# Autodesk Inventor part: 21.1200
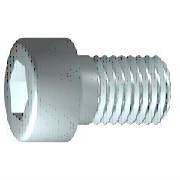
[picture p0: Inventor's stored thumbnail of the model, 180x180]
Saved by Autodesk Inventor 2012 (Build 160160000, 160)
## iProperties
Created: 2006-02
Part Number: 21.1200
Material: Steel, Mild
Description: M8 x 16 SHCS
Document SubType Name: Modeling
Standard: DIN 7984
Designer: Andy Moles
Standards Organization: DIN
Language: en-US
Size Designation: M8 x 16
Categories: <MemberInstance><Categories><Category DisplayName="Fasteners" InternalName="e4da775c-781d-43d5-af7c-5136215cf5a6" Mnemonic="FSTN"><Category DisplayName="Bolts"
Density: 7.86 g/cm^3
Mass: 10.6827 g
Surface Area: 9.17139 cm^2
Volume: 1.35912 cm^3
Vendor: S
Author: Andy Moles
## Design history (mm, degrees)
body "Solid1"
workplane "Work Plane1"
revolve "Body" stored, may be unused: angle "d10" = 90 deg
sketch "Sketch2"
  geometry: L1 (0, -7.8)-(0, 10.4) reference; L2 (-7.8, 0)-(10.4, 0) reference; L3 (2.887, 0)-(1.443, -2.5); L4 (1.443, -2.5)-(-1.443, -2.5); L5 (-1.443, -2.5)-(-2.887, 0); L6 (-2.887, 0)-(-1.443, 2.5); L7 (-1.443, 2.5)-(1.443, 2.5); L8 (1.443, 2.5)-(2.887, 0); 2 further points
  constraints: 12 end point, 1 coincident, 1 horizontal alignment, 1 point on line, 12 other
extrude "Slot" join sketch "Sketch2" stored distance "d11" = 10; taper "d12" = 0 deg
fillet "Fillet1" dims "d17" = 0.8 (= RR)
feature "Thread" dims "d13" = 16, "d14" = 0
chamfer "Chamfer1" distance "d15" = 0.76681 (= -0.5 x SPD + 0.5 x GD); stored, may be unused: second distance "d16" = 0.76681 (= GUL), angle "d27" = 45 deg
sketch "Sketch1"
  geometry: L1 (0.467, 0)-(16, 0); L2 (16, 0)-(16, 4); L3 (16, 4)-(3.75, 4); L4 (3.75, 4)-(2.983, 4); L5 (2.983, 4)-(0, 4); L6 (0, 4)-(0, 6.5); L7 (0, 6.5)-(-5, 6.5); L8 (-5, 6.5)-(-5, 2.887); L9 (-5, 2.887)-(-1.2, 2.887); L10 (-1.2, 2.887)-(0.467, 0); L11 (-7.1, 0)-(22.3, 0) reference; L12 (0, -0.65)-(0, 8.45) reference; L13 (3.75, 4)-(0, 4)
  constraints: 22 end point, 6 parallel, 2 collinear, 2 perpendicular, 1 horizontal, 1 point on line
  dimensions: "d1" = 12.25 distance from line of L3.end L2 (= GEL); "d2" = 0.76691 distance of L4.end L3.end (computed from GAL); "d3" = 5 distance between parallel lines of L8 L6 (= KOH); "d4" = 3.8 distance of L8.end L9.end (= INTI); "d5" = 60 deg angle of L10 L1; "d6" = 8 diameter of L3 L1 (= GD); "d7" = 8 diameter of L5 L1 (= BDM); "d8" = 5.7735 diameter of L9 L1 (= 1.1547 x SW); "d9" = 13 diameter of L7 L1 (= KOD); "d26" = 16 distance between parallel lines of L12 L2 (= NLG)
other parameters: "GD" = 8 (= NND) [user parameter; used in 2 equation terms], "NLG" = 16 [user parameter; used in 1 equation term], "GEL" = 12.25 [user parameter; used in 1 equation term], "KOD" = 13 [user parameter; used in 1 equation term], "KOH" = 5 [user parameter; used in 1 equation term], "INTI" = 3.8 [user parameter; used in 1 equation term], "GAL" = 0.76681 (= 0.61345 x PTC) [user parameter; used in 1 equation term], "GUL" = 0.76681 (= 0.61345 x PTC) [user parameter; used in 1 equation term], "BDM" = 8 (= NND) [user parameter; used in 1 equation term], "SW" = 5 [user parameter; used in 2 equation terms], "RR" = 0.8 [user parameter; used in 1 equation term], "SPD" = 6.46637 (= NND - 1.2269 x PTC) [user parameter; used in 1 equation term], "d19" = 0, "d28" = 0, "d29" = 0, "TOA" = 30 deg [user parameter], "GD1" = 6.46637 (= THREADDIA - 1.2269 x PTC) [user parameter], "THREADDIA" = 8 [user parameter; used in 1 equation term], "FAWI" = 45 deg [user parameter], "ANG" = 120 deg [user parameter], "TPU" = 8 (computed from PTC) [user parameter], "PTC" = 1.25 [user parameter; used in 5 equation terms], "NND" = 8 [user parameter; used in 3 equation terms], "E0" = 5.775 (= 1.155 x SW) [user parameter]
